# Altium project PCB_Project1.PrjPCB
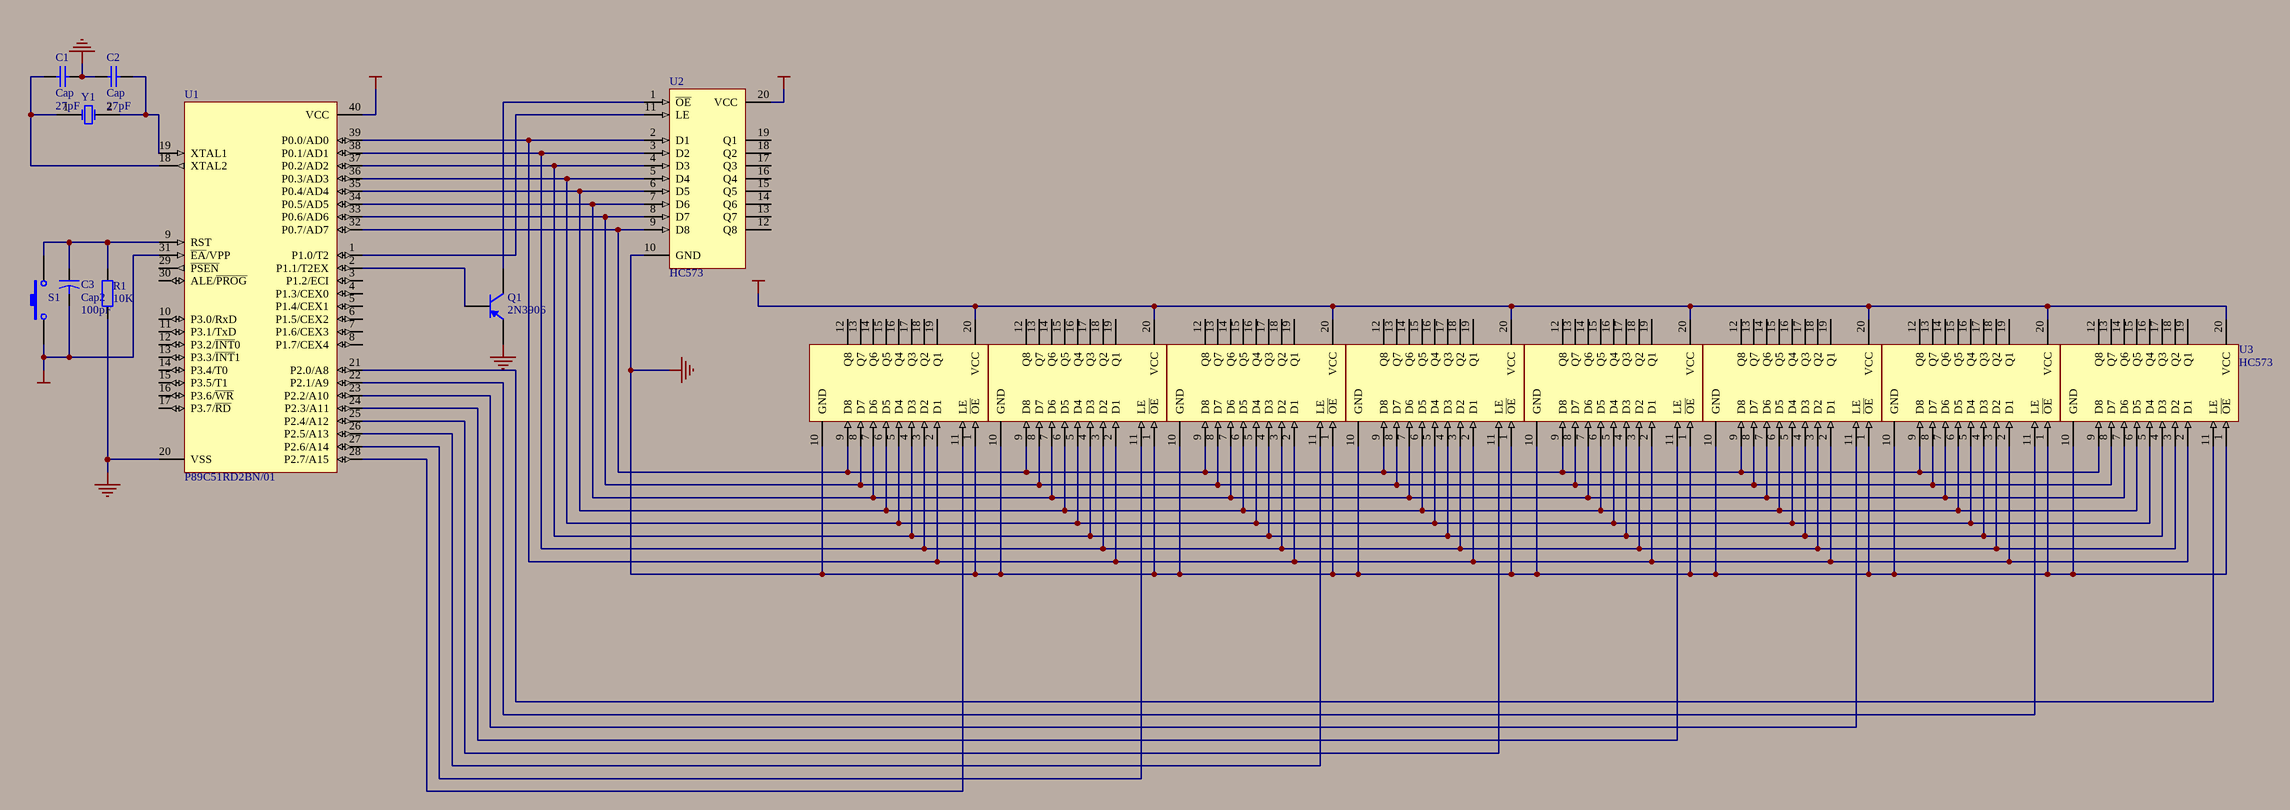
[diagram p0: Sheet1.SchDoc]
1 sheet, 17 parts. Net scope: global (net labels, ports and power ports of the same name join across sheets).

## Sheet Sheet1.SchDoc
size A2

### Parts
7  HC573  [CDIP20]
C1  Cap  value 27pF  [RAD-0.3]
C2  Cap  value 27pF  [RAD-0.3]
C3  Cap2  value 100pF  [CAPR5-4X5]
Q1  2N3906  [BCY-W3/E4]
R1  value 10K  [AXIAL-0.4]  (hidden comment: Res2)
S1  SW-PB  [SPST-2]  (value not drawn)
U1  P89C51RD2BN/01  [SOT129-1]
U2  HC573  [CDIP20]
U3  HC573  [CDIP20]
U4  HC573  [CDIP20]
U5  HC573  [CDIP20]
U6  HC573  [CDIP20]
U8  HC573  [CDIP20]
U9  HC573  [CDIP20]
U10  HC573  [CDIP20]
Y1  XTAL  [BCY-W2/D3.1]  (value not drawn)

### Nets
GND: 7.1(~{OE}) 7.10(GND) C1.2 C2.1 Q1.1(E) R1.1 U1.20(VSS) U2.10(GND) U3.1(~{OE}) U3.10(GND) U4.1(~{OE}) U4.10(GND) U5.1(~{OE}) U5.10(GND) U6.1(~{OE}) U6.10(GND) U8.1(~{OE}) U8.10(GND) U9.1(~{OE}) U9.10(GND) U10.1(~{OE}) U10.10(GND)
VCC: 7.20(VCC) C3.2 S1.1 U1.31(~{EA}/VPP) U1.40(VCC) U2.20(VCC) U3.20(VCC) U4.20(VCC) U5.20(VCC) U6.20(VCC) U8.20(VCC) U9.20(VCC) U10.20(VCC)
Net7_2: 7.2(D1) U1.39(P0.0/AD0) U2.2(D1) U3.2(D1) U4.2(D1) U5.2(D1) U6.2(D1) U8.2(D1) U9.2(D1) U10.2(D1)
Net7_3: 7.3(D2) U1.38(P0.1/AD1) U2.3(D2) U3.3(D2) U4.3(D2) U5.3(D2) U6.3(D2) U8.3(D2) U9.3(D2) U10.3(D2)
Net7_4: 7.4(D3) U1.37(P0.2/AD2) U2.4(D3) U3.4(D3) U4.4(D3) U5.4(D3) U6.4(D3) U8.4(D3) U9.4(D3) U10.4(D3)
Net7_5: 7.5(D4) U1.36(P0.3/AD3) U2.5(D4) U3.5(D4) U4.5(D4) U5.5(D4) U6.5(D4) U8.5(D4) U9.5(D4) U10.5(D4)
Net7_6: 7.6(D5) U1.35(P0.4/AD4) U2.6(D5) U3.6(D5) U4.6(D5) U5.6(D5) U6.6(D5) U8.6(D5) U9.6(D5) U10.6(D5)
Net7_7: 7.7(D6) U1.34(P0.5/AD5) U2.7(D6) U3.7(D6) U4.7(D6) U5.7(D6) U6.7(D6) U8.7(D6) U9.7(D6) U10.7(D6)
Net7_8: 7.8(D7) U1.33(P0.6/AD6) U2.8(D7) U3.8(D7) U4.8(D7) U5.8(D7) U6.8(D7) U8.8(D7) U9.8(D7) U10.8(D7)
Net7_9: 7.9(D8) U1.32(P0.7/AD7) U2.9(D8) U3.9(D8) U4.9(D8) U5.9(D8) U6.9(D8) U8.9(D8) U9.9(D8) U10.9(D8)
Net7_11: 7.11(LE) U1.25(P2.4/A12)
NetC1_1: C1.1 U1.18(XTAL2) Y1.1(OSC1)
NetC2_2: C2.2 U1.19(XTAL1) Y1.2(OSC2)
NetC3_1: C3.1 R1.2 S1.2 U1.9(RST)
NetQ1_2: Q1.2(B) U1.2(P1.1/T2EX)
NetQ1_3: Q1.3(C) U2.1(~{OE})
NetU1_1: U1.1(P1.0/T2) U2.11(LE)
NetU1_21: U1.21(P2.0/A8) U3.11(LE)
NetU1_22: U1.22(P2.1/A9) U4.11(LE)
NetU1_23: U1.23(P2.2/A10) U5.11(LE)
NetU1_24: U1.24(P2.3/A11) U6.11(LE)
NetU1_26: U1.26(P2.5/A13) U8.11(LE)
NetU1_27: U1.27(P2.6/A14) U9.11(LE)
NetU1_28: U1.28(P2.7/A15) U10.11(LE)

Not connected (* = marked no-connect by the designer): 7 12(Q8) 13(Q7) 14(Q6) 15(Q5) 16(Q4) 17(Q3) 18(Q2) 19(Q1); U1 3(P1.2/ECI) 4(P1.3/CEX0) 5(P1.4/CEX1) 6(P1.5/CEX2) 7(P1.6/CEX3) 8(P1.7/CEX4) 10(P3.0/RxD) 11(P3.1/TxD) 12(P3.2/~{INT}0) 13(P3.3/~{INT}1) 14(P3.4/T0) 15(P3.5/T1) 16(P3.6/~{WR}) 17(P3.7/~{RD}) 29(~{PSEN}) 30(ALE/~{PROG}); U2 12(Q8) 13(Q7) 14(Q6) 15(Q5) 16(Q4) 17(Q3) 18(Q2) 19(Q1); U3 12(Q8) 13(Q7) 14(Q6) 15(Q5) 16(Q4) 17(Q3) 18(Q2) 19(Q1); U4 12(Q8) 13(Q7) 14(Q6) 15(Q5) 16(Q4) 17(Q3) 18(Q2) 19(Q1); U5 12(Q8) 13(Q7) 14(Q6) 15(Q5) 16(Q4) 17(Q3) 18(Q2) 19(Q1); U6 12(Q8) 13(Q7) 14(Q6) 15(Q5) 16(Q4) 17(Q3) 18(Q2) 19(Q1); U8 12(Q8) 13(Q7) 14(Q6) 15(Q5) 16(Q4) 17(Q3) 18(Q2) 19(Q1); U9 12(Q8) 13(Q7) 14(Q6) 15(Q5) 16(Q4) 17(Q3) 18(Q2) 19(Q1); U10 12(Q8) 13(Q7) 14(Q6) 15(Q5) 16(Q4) 17(Q3) 18(Q2) 19(Q1)

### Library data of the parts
7 U2-U6 U8-U10 = M54HC573F1R: Octal D-Type Latch with 3-State Output Non-Inverting
C1 C2 = Cap: Capacitor
C3 = Cap2: Capacitor
Q1 = 2N3906: PNP General Purpose Amplifier
R1 = Res2: Resistor
S1 = SW-PB: Switch
U1 = P89C51RD2BN/01: 80C51 8-Bit Flash Microcontroller Family, 64 kB ISP/IAP Flash with 1 kB RAM.
Y1 = XTAL: Crystal Oscillator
